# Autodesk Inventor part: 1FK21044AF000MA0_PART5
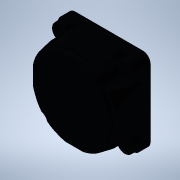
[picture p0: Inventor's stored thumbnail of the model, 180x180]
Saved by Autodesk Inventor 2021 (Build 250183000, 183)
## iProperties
Created: 2025-04
Part Number: 1FK21044AF000MA0_PART5
Material: Generic
Catalog Web Link: www.3dfindit.com
Description: -Servo synchronous motor
Document SubType Name: Modeling
Designer: psAdmin
Mass: 3.92604 g
Surface Area: 17.9521 cm^2
Volume: 3.92604 cm^3
Density: 1 g/cm^3
Appearance: PSOLRGB-48-56-69
Category: PARTsolutions
Title: 1FK21044AF000MA0_PART5
Author: Cadenas PARTsolutions
Comments: Servo synchronous motor
Sending System: PARTsolutions
Preprocessor: ST-DEVELOPER v19.3
PSOL_IDENT_0: {$CADENAS_DATA/23d-libs/siemens_ag/_cat_/39/c4/1fk21044af000ma0.prj},213 {VTYP=3D},{NB=1FK21044AF000
PSOL_IDENT_1: MA0_PART5},{LINA=1FK21044AF000MA0_PART5},{NN=1FK21044AF000MA0_PART5},{NOPRJ=TRUE},{DATE=19.08.2025 1
PSOL_IDENT_2: 4:00:33},{GEOMDATE=30.07.2025 02:02:22},{VERSION=},{LINEID=10},{WBVAR=},{WBNUMERIC=}  {NB=1FK21044AF
PSOL_IDENT_3: 000MA0_PART5},{LINA=1FK21044AF000MA0_PART5},{KT=DUMMY},{PREVIEW=../../../_pool_/cb/72/p_d211_xx_0043
PSOL_IDENT_4: 4j.png},{DESCSHORT=SIMOTICS S-1FK2 HD, SINAMICS S210 3AC 400V-480V, 1.27 Nm, 3000 rpm},{DESCLONG=SIM
PSOL_IDENT_5: OTICS S-1FK2 HD servo motor M0=1.27 Nm; PN = 0.4 kW at nN=3000 rpm (380-480 V); PN = 0.2 kW at nN=15
PSOL_IDENT_6: 00 rpm (200-240 V); degree of protection IP64; cylindrical shaft D19x40mm; absolute encoder 22-bit +
PSOL_IDENT_7: 12-bit multiturn (encoder AM22DQC); with OCC interface; plug size M17, rotatable; SIMOTICS S-1FK2 s
PSOL_IDENT_8: ervomotorfor a wide range of uses in industrial environments. SIMOTICS S‑1FK2 servomotors are compac
PSOL_IDENT_9: t synchronous motors with a high dynamic performance that set themselves apart as a result of their
PSOL_IDENT_10: high power density, degree of protection and overload capability. The motors are available in two va
PSOL_IDENT_11: riants: as High Dynamic variant (highest dynamic performance as a result of the low intrinsic moment
PSOL_IDENT_12: of inertia for applications demanding a high dynamic performance with low moved masses) - and as Co
PSOL_IDENT_13: mpact variant (precise and stable closed-loop control for medium up to large moved masses as a resul
PSOL_IDENT_14: t of a medium intrinsic moment of inertia). SIMOTICSS‑1FK2 servomotors fully exploit their strengths
PSOL_IDENT_15: in a system with the SINAMICSS210 frequency converter and simple connection using the one cable con
PSOL_IDENT_16: nection (OCC). Advantages include the short control and positioning times, fast and precise correcti
PSOL_IDENT_17: on of disturbing quantities as well as stable control with a high dynamic performance. The servo mot
PSOL_IDENT_18: ors can be configured to address a wide range of requirements. For example with and without holding
PSOL_IDENT_19: brake, IP64 or IP65 degree of protection, singleturn or multiturn absolute encoders - to name just a
PSOL_IDENT_20: few. Further, the servomotors are available in different shaft heights extending from 20 to 100. A
PSOL_IDENT_21: shaft sealing ring is available to achieve an IP65 degree of protection and for subsequent mounting
PSOL_IDENT_22: at the motor or as spare part. SIMOTICS - the optimum motor for each and every motion control applic
PSOL_IDENT_23: ation.},{INTNO=804766906428},{SUPPLIERALTNO=1FK2104-4AF00-0MA0},{MANUID=1FK21044AF000MA0},{MANUNAME=
PSOL_IDENT_24: Siemens},{MANUTYPEDESC=Synchronous motor 1FK2-HD 1.27 NM},{AAU732=SIMOTICS},{AAO057=S-1FK2},{AAU734=
PSOL_IDENT_25: SIMOTICS S-1FK2 HD servo motor M0=1.27 Nm; PN = 0.4 kW at nN=3000 rpm (380-480 V); PN = 0.2 kW at nN=
PSOL_IDENT_26: 1500 rpm (200-240 V); degree of protection IP64; cylindrical shaft D19x40mm; absolute encoder 22-bit
PSOL_IDENT_27: + 12-bit multiturn (encoder AM22DQC); with OCC interface; plug size M17, rotatable;},{AAW338=Synchr
PSOL_IDENT_28: onous motor 1FK2-HD 1.27 NM},{AAO742=SIMOTICS},{AAO663=4042948693322},{NOCUPEROU=1},{PRICEQUANTITY=1
PSOL_IDENT_29: },{QUANTITYMIN=1},{QUANTITYINT=1},{CTN=85015100},{COO=DE},{AAO676=1FK2104-4AF00-0MA0},{AAO677=Siemen
PSOL_IDENT_30: s AG},{ORDERUNIT=C62},{CONTENTUNIT=C62}
NB: 1FK21044AF000MA0_PART5
NT: Servo synchronous motor
NBSYN: $MANUID._PART5
LINA: 1FK21044AF000MA0_PART5
CATALOG: SIEMENS
PREVIEW: ../../../_pool_/cb/72/p_d211_xx_00434j.png
DESCSHORT: SIMOTICS S-1FK2 HD, SINAMICS S210 3AC 400V-480V, 1.27 Nm, 3000 rpm
DESCLONG: SIMOTICS S-1FK2 HD servo motor M0=1.27 Nm; PN = 0.4 kW at nN=3000 rpm (380-480 V); PN = 0.2 kW at nN=1500 rpm (200-240 V); degree of protection IP64; cylindrica
INTNO: 804766906428
SUPPLIERALTNO: 1FK2104-4AF00-0MA0
MANUID: 1FK21044AF000MA0
MANUNAME: Siemens
MANUTYPEDESC: Synchronous motor 1FK2-HD 1.27 NM
AAU732: SIMOTICS
AAO057: S-1FK2
AAU734: SIMOTICS S-1FK2 HD servo motor M0=1.27 Nm; PN = 0.4 kW at nN=3000 rpm (380-480 V); PN = 0.2 kW at nN=1500 rpm (200-240 V); degree of protection IP64; cylindrica
AAW338: Synchronous motor 1FK2-HD 1.27 NM
AAO742: SIMOTICS
AAO663: 4042948693322.0
NOCUPEROU: 1
PRICEQUANTITY: 1
QUANTITYMIN: 1
QUANTITYINT: 1
CTN: 85015100
COO: DE
ARTICLENO: 1FK21044AF000MA0_PART5
BOMINFO: 1FK21044AF000MA0_PART5
CREATOR: CADENAS GmbH
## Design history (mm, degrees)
feature "2025_04_17_15_01_27_0975"
body "Solid1"
